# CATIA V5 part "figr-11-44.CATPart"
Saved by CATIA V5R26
Part number: Part1
Bounding box of the stored display mesh (mm): x -59 to 59, y -60 to 60, z 0 to 39.8
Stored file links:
  D:\_Deepak\CATIA\CATIA V5-6R2016_Deepak\Resources\Part files\Partfiles\c11_catia_v5_6r2016_prt\figr-11-44.CATPart
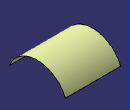
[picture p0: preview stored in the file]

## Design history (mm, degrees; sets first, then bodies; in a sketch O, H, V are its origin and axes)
AxisSystem1: origin (0, 0, 0), X (1, 0, 0), Y (0, 1, 0), Z (0, 0, 1)
AxisSystem2: origin (0, 150, -30), X (1, 0, 0), Y (0, 1, 0), Z (0, 0, 1)
Set1
  Extrude1: Element1 Sketch2, Lim1 59, Lim2 59, Direction yz-plane
  Sketch1 on yz-plane, origin (0, 0, 0), H (0, 1, 0), V (0, 0, 1)
    point P1 (150, -30)
  AxisToAxis1: ToTransfor Extrude1, AxisOrigin AxisSystem1, Axis AxisSystem2
Body1 (main body)
  Sketch2 on yz-plane, origin (0, 0, 0), H (0, 1, 0), V (0, 0, 1)
    arc A1 centre (0, -25) radius 65 from (-60, 0) to (60, 0) cw
    point P2 (-60, 0)
    point P3 (60, 0)
    coincidence: P2 H, P3 H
